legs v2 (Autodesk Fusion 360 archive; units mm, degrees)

design "legs" references "solenoid_cover"
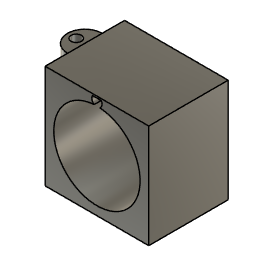
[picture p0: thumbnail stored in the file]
component_insert "Component Insert"
sketch "Sketch2" plane through (0, 0, 28) normal (0, 0, 1) x axis (-1, 0, 0)
  line L1 (0, 0) -> (0, 23)
  line L2 (30, 0) -> (0, 0)
  line L3 (30, 23) -> (30, 0)
  line L4 (0, 23) -> (30, 23)
  circle C1 centre (15, 0) radius 5
  circle C2 centre (30, 11.5) radius 5
  circle C3 centre (15, -2.5) radius 1.5
  circle C4 centre (32.5, 11.5) radius 1.5
  point P6 (15, 0)
  point P7 (30, 11.5)
  midpoint L2 P6
  midpoint L3 P7
  dimension "d5" diameter C1 = 10
  dimension "d6" diameter C2 = 10
  dimension "d7" diameter C3 = 3
  dimension "d8" diameter C4 = 3
extrude "Extrude3" new body sketch "Sketch2" profile of L3 C2 C4 against normal blind 5
extrude "Extrude1" new body of existing geometry blind 20
sketch "Sketch1" plane through (0, -23, 0) normal (0, -1, 0) x axis (1, 0, 0)
  line L1 (-13.7158, 27.5) -> (-16.2842, 27.5)
  line L2 (0, -2) -> (-30, -2)
  line L3 (0, 28) -> (0, -2)
  line L4 (-30, 28) -> (0, 28)
  line L5 (-30, -2) -> (-30, 28)
  line L6 (-10, 28) -> (-19, 28)
  line L7 (-10, 22) -> (-10, 28)
  line L8 (-19, 22) -> (-10, 22)
  line L9 (-19, 28) -> (-19, 22)
  arc A1 centre (-15, 26.7249) radius 1.5 clockwise from (-13.7158, 27.5) to (-14.1742, 25.4727)
  arc A2 centre (-15, 13) radius 12.5 clockwise from (-14.1742, 25.4727) to (-15.8258, 25.4727)
  arc A3 centre (-15, 26.7249) radius 1.5 clockwise from (-15.8258, 25.4727) to (-16.2842, 27.5)
  point P12 (-19, 28)
  horizontal L6
  vertical L7
  horizontal L8
  vertical L9
  coincident L4 P12
extrude "Extrude2" add sketch "Sketch1" profile of A1 A2 A3 L1 L7 L8 L9 against normal blind 23

design "solenoid_cover"
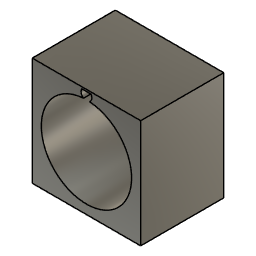
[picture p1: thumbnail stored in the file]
sketch "Sketch1" plane through (0, 0, 0) normal (0, 0, 1) x axis (1, 0, 0)
  line L1 (-30, 0) -> (0, 0)
  line L2 (-30, -23) -> (-30, 0)
  line L3 (0, -23) -> (-30, -23)
  line L4 (0, 0) -> (0, -23)
  point P1 (0, 0)
  point P2 (0, 0)
  point P3 (-30, 0)
  point P5 (0, -23)
  horizontal L1
  vertical L2
  horizontal L3
  vertical L4
  coincident P1 P2
  dimension "d1" distance P2 P3 = 30
  dimension "d2" distance P2 P5 = 23
extrude "Extrude1" new body sketch "Sketch1" along normal blind 30
sketch "Sketch2" plane through (0, -23, 0) normal (0, -1, 0) x axis (1, 0, 0)
  line L1 (0, 0) -> (-30, 0)
  line L2 (0, 30) -> (0, 0)
  line L3 (-30, 30) -> (0, 30)
  line L4 (-30, 0) -> (-30, 30)
  line L5 (-15, 2.5) -> (-15, 0)
  line L6 (-15, 27.5) -> (-15, 30)
  circle C1 centre (-15, 15) radius 12.5
  point P6 (-15, 0)
  point P8 (-15, 30)
  point P7 (-15, 2.5)
  point P9 (-15, 27.5)
  midpoint L1 P6
  perpendicular L1 L5
  midpoint L3 P8
  perpendicular L3 L6
  dimension "d5" distance P6 P7 = 2.5
  dimension "d6" distance P8 P9 = 2.5
  dimension "d7" diameter C1 = 25
extrude "Extrude2" cut sketch "Sketch2" profile of C1 against normal blind 20
sketch "Sketch3" plane through (0, -23, 0) normal (0, -1, 0) x axis (1, 0, 0)
  line L1 (0, 0) -> (-30, 0)
  line L2 (0, 30) -> (0, 0)
  line L3 (-30, 30) -> (0, 30)
  line L4 (-30, 0) -> (-30, 30)
  line L5 (-16.2842, 29.5) -> (-13.7158, 29.5)
  circle C1 centre (-15, 15) radius 12.5
  circle C2 centre (-15, 28.7249) radius 1.5
  point P8 (-13.7158, 29.5)
  point P9 (-16.2842, 29.5)
  coincident C2 P8
  coincident C2 P9
  parallel L3 L5
  dimension "d10" diameter C2 = 3
extrude "Extrude3" cut sketch "Sketch3" profile of C1 C2 L5 against normal blind 30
